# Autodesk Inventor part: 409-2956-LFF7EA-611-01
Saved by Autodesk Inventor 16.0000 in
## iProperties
Created: 2010-06
Part Number: 409-2956-LFF7EA-611-01
Cost Center: 0 lbmass
Material: A36 STEEL PLATE
Document SubType Name: Sheet Metal
Designer: S. Boerckel
Authority: 0 in^3
Mass: 125025 g
Surface Area: 17471.2 cm^2
Volume: 15906.5 cm^3
Density: 7.86 g/cm^3
Sheet Metal Rule: 3/4"Thk
Description: PUMP MOUNT PLATE
Flat Pattern Width: 68.58 cm
Flat Pattern Length: 121.92 cm
Flat Pattern Area: 8361.27 cm^2
Sheet Metal Width: 47.0000 in
Sheet Metal Length: 752.0000 in^2
User Status: BURN/DRILL
SaveDate: 2008-01-15
SaveTime: 10:24
FileName: Sheet Metal
Wide: =<Flat Pattern Width>cm
Length: =<Flat Pattern Length>cm
Thickness: 0.7500 in
SMR: =<Sheet Metal Rule> - <Material>
Author: S. Boerckel
Revision Number: 0
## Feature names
1. Hole1
2. Plate1
